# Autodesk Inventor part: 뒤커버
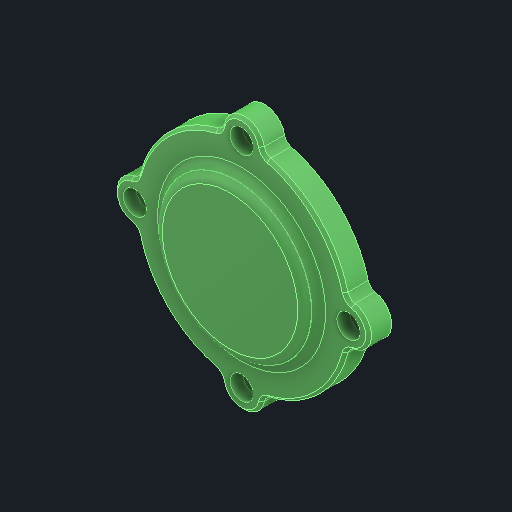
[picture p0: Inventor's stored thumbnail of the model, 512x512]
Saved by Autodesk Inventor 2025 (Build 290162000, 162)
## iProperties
Created: 2025-08
Part Number: 뒤커버
Material: 알루미늄 6061
Document SubType Name: Modeling
Designer: infra14
Density: 2.71 g/cm^3
Appearance: 기본값
Company: 한국ATC센터
Author: jhkim
Sending System: Autodesk Inventor 2026
Preprocessor: ST-DEVELOPER v20.1
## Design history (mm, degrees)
feature "솔리드1"
node "솔리드2"
